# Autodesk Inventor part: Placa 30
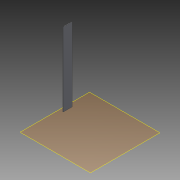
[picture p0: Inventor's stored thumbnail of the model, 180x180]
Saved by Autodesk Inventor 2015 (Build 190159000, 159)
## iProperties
Created: 2015-04
Part Number: Placa 30
Material: Generic
Document SubType Name: Modeling
Designer: suporte
Density: 1 g/cm^3
Appearance: Default
Author: suporte
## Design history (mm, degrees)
workplane "Work Plane1"
sketch "Sketch1"
  geometry: L1 (-887.5, 125)-(-900, 125) reference; L2 (-887.5, 125)-(-900, 125); L3 (-900, 125)-(-900, 425); L4 (-900, 425)-(-887.5, 425); L5 (-887.5, 425)-(-887.5, 125); 1 further point
  constraints: 8 end point, 2 parallel, 1 horizontal, 1 perpendicular
  dimensions: "d0" = 12.5 distance of L3.end L4.end; "d1" = 300 distance of L2.end L3.end
extrude "Extrusion1" new body sketch "Sketch1" distance "d2" = 2100; taper "d3" = 0 deg
body "Solid1"
node "Reference1"
